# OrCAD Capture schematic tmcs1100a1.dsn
size A; title: TMCS1100 1% High-Precision, Basic Isolation Hall-Effect Current Sensor; rev: A; note: SBOS820
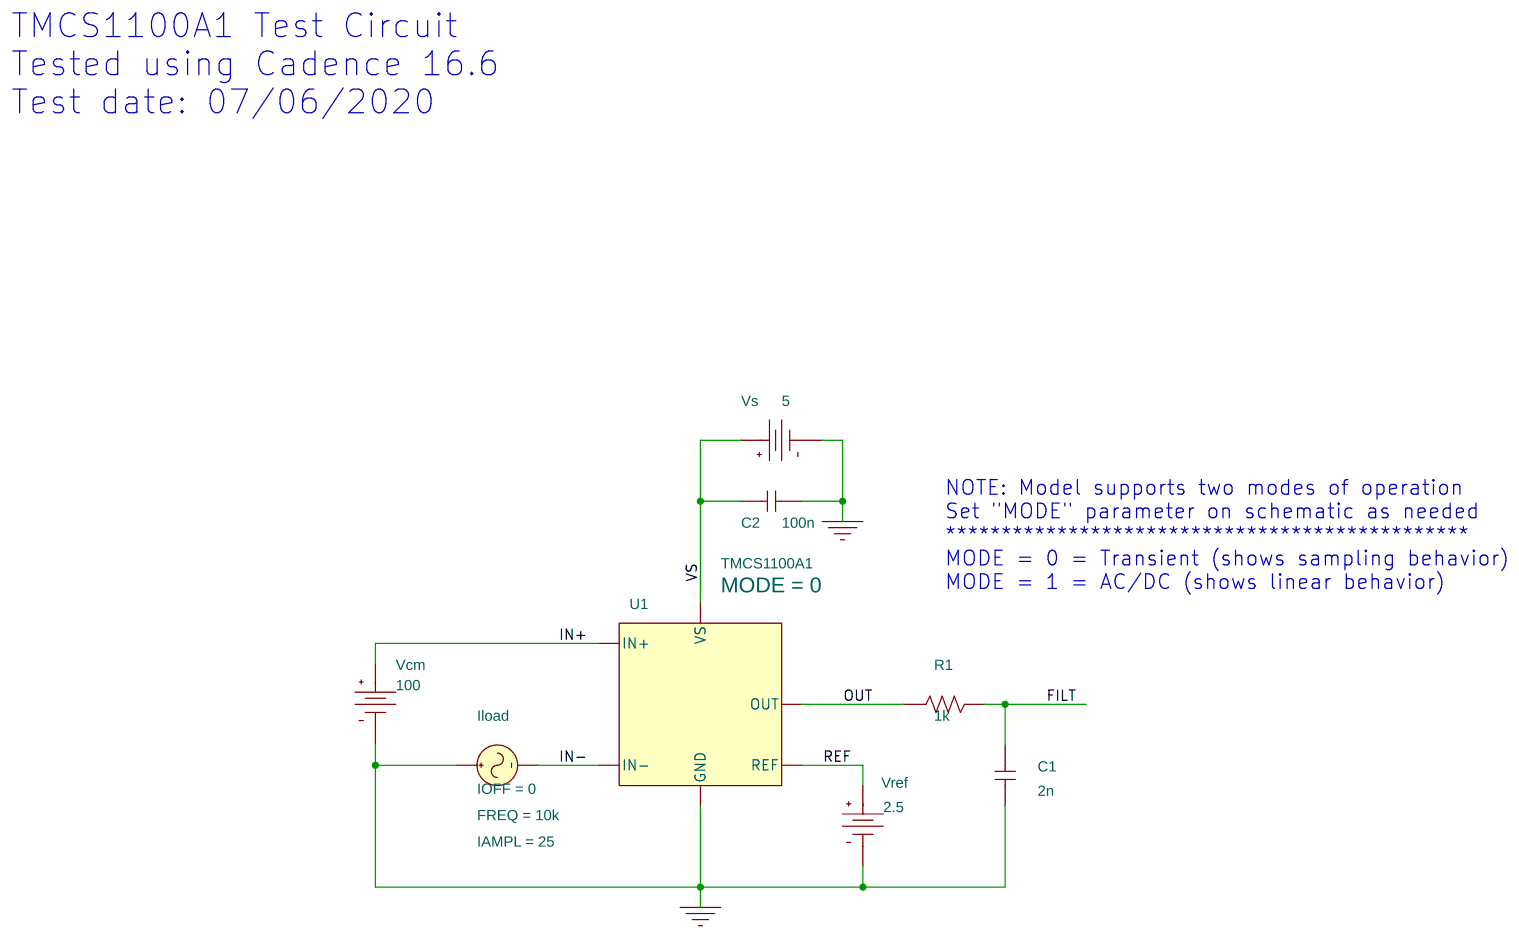
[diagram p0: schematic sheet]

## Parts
C1  2n  [RAD/CK05]
C2  100n  [RAD/CK05]
Iload  ISIN
R1  1k  [AX/RC05]
U1  TMCS1100A1
Vcm  VDC
Vref  VDC
Vs  VDC

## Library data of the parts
C1 C2 = C
Iload = ISIN: FREQ: 10k; IAMPL: 25; IOFF: 0
R1 = R
U1 = TMCS1100A1: MODE: 0
Vcm = VDC: DC: 100
Vref = VDC: DC: 2.5
Vs = VDC: DC: 5

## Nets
0: C1.1 C2.1 Iload.1(+) U1.GND Vcm.1(-) Vref.1(-) Vs.1(-)
FILT: C1.2 R1.2
IN+: U1.IN+ Vcm.0(+)
IN-: Iload.2(-) U1.IN-
OUT: R1.1 U1.OUT
REF: U1.REF Vref.0(+)
VS: C2.2 U1.VS Vs.0(+)

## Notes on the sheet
- TMCS1100A1 Test Circuit
  Tested using Cadence 16.6
  Test date: 07/06/2020
- NOTE: Model supports two modes of operation
  Set "MODE" parameter on schematic as needed
  ***********************************************
  MODE = 0 = Transient (shows sampling behavior)
  MODE = 1 = AC/DC (shows linear behavior)
